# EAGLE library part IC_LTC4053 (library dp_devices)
USB Compatible Li-Ion Battery Charger
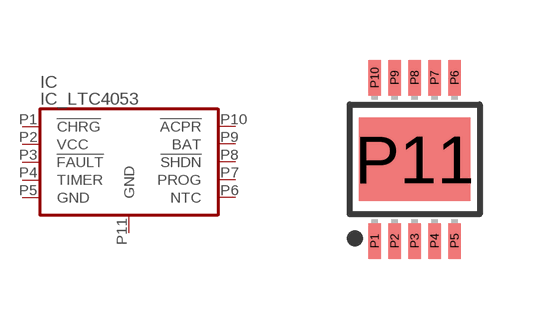
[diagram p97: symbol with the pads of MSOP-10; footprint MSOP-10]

Designator prefix IC

## IC_LTC4053-MSOP-10  [MSOP-10]
P1  !CHRG  pas
P2  VCC  pwr
P3  !FAULT  pas
P4  TIMER  pas
P5  GND  pwr
P6  NTC  pas
P7  PROG  pas
P8  !SHDN  pas
P9  BAT  pas
P10  !ACPR  pas
P11  GND  pwr

## Footprint MSOP-10 (pad centres in mm)
Exposed Pad 0.5mm pitch
smd 0.31 x 0.89: P1 -1,-2.045; P2 -0.5,-2.045; P3 0,-2.045; P4 0.5,-2.045; P5 1,-2.045; P6 1,2.045; P7 0.5,2.045; P8 0,2.045; P9 -0.5,2.045; P10 -1,2.045
smd 2.79 x 2.08: P11 0,0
